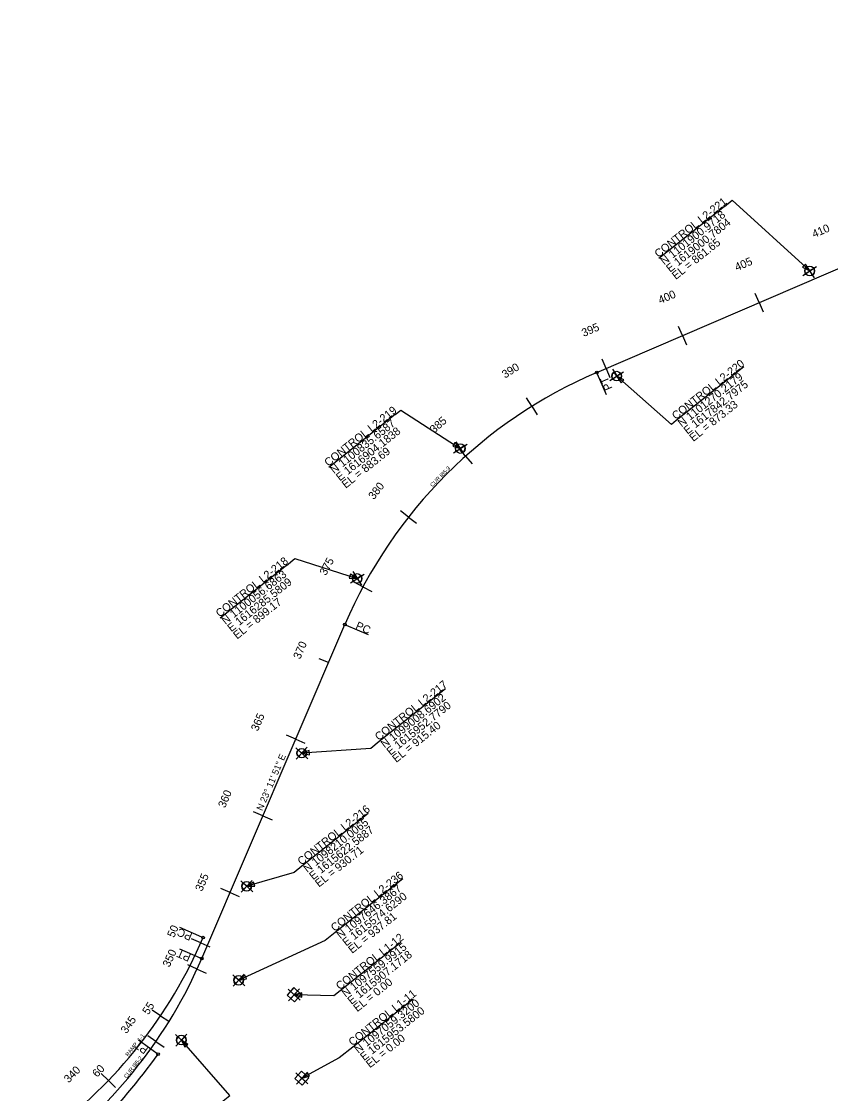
# Model space of a CAD drawing. Extents: x 1603447 to 1622636, y 1083818 to 1103958.
# Drawn here: x 1614271 to 1619126, y 1096967 to 1103398 of the extents above; entities that cross this region are included whole.
import ezdxf

# ---------------------------------------------------------------- set-up
doc = ezdxf.new("R2010")
doc.units = 0
for name, color, linetype in [('Level 1', 7, 'Continuous'), ('RD_HC_Points', 7, 'Continuous'), ('RD_HC_SUR_Bearing_TX400', 7, 'Continuous'), ('RD_HC_SUR_CL400', 7, 'Continuous'), ('RD_HC_SUR_PC_PT_400', 7, 'Continuous'), ('RD_HC_SUR_Tic400', 7, 'Continuous'), ('RD_HC_SUR_TX_Sta400', 7, 'Continuous'), ('RD_SHT_Misc1', 7, 'Continuous'), ('RD_TX_Misc1', 7, 'Continuous')]:
    doc.layers.add(name, color=color, linetype=linetype)

msp = doc.modelspace()

# ---------------------------------------------------------------- linework, layer by layer
at = {"layer": 'RD_HC_Points'}
for p, q in [((1618489.5, 1102287.9), (1618095.7, 1101974.7)), ((1618605.8, 1101325.6), (1618200.3, 1101003.1)), ((1616512.6, 1101039.1), (1616114.6, 1100722.5)), ((1615860.9, 1100134.8), (1615462.9, 1099818.2)), ((1616816.1, 1099394.5), (1616417.9, 1099077.8)), ((1616352.2, 1098647.2), (1615954, 1098330.5)), ((1616558.5, 1098255.1), (1616153.1, 1097932.6)), ((1616548.3, 1097872.8), (1616183.9, 1097582.9)), ((1616621.1, 1097533.5), (1616259.8, 1097246.2))]:
    msp.add_line(p, q, dxfattribs=at)
for points in [[(1618489.5, 1102287.9), (1618535.6, 1102324.6), (1619000.8, 1101901)], [(1618200.3, 1101003.1), (1618171.1, 1100979.8), (1617842.8, 1101270.2)], [(1616512.6, 1101039.1), (1616547.5, 1101066.8), (1616904.2, 1100835.7)], [(1615860.9, 1100134.8), (1615912.1, 1100175.5), (1616285.6, 1100056.7)], [(1616417.9, 1099077.8), (1616366.7, 1099037.1), (1615952.8, 1099008.7)], [(1615954, 1098330.5), (1615907.3, 1098293.4), (1615622.6, 1098210)], [(1616153.1, 1097932.6), (1616094, 1097885.6), (1615574.6, 1097646.4)], [(1616183.9, 1097582.9), (1616145.4, 1097552.3), (1615907.2, 1097560)], [(1615470.7, 1096915.2), (1615521.2, 1096955.3), (1615230.5, 1097288.1)], [(1616259.8, 1097246.2), (1616177.3, 1097180.5), (1615953.6, 1097059.3)]]:
    msp.add_lwpolyline(points, dxfattribs=at)
for points in [[(1618958.1, 1101923), (1619000.8, 1101901), (1618974.9, 1101941.4)], [(1617885.8, 1101248.8), (1617842.8, 1101270.2), (1617869.3, 1101230.2)], [(1616858.5, 1100850.4), (1616904.2, 1100835.7), (1616872, 1100871.3)], [(1616237.6, 1100058.9), (1616285.6, 1100056.7), (1616245.2, 1100082.6)], [(1615998.2, 1099024.3), (1615952.8, 1099008.7), (1615999.9, 1098999.5)], [(1615663.6, 1098235), (1615622.6, 1098210), (1615670.6, 1098211.1)], [(1615611.5, 1097677.1), (1615574.6, 1097646.4), (1615621.9, 1097654.5)], [(1615953.9, 1097570.9), (1615907.2, 1097560), (1615953.1, 1097546.1)], [(1615270.3, 1097261.4), (1615230.5, 1097288.1), (1615251.6, 1097245)], [(1615988.4, 1097092.3), (1615953.6, 1097059.3), (1616000.3, 1097070.5)]]:
    msp.add_lwpolyline(points, close=True, dxfattribs=at)
at = {"layer": 'RD_HC_SUR_CL400'}
for p, q in [((1617722.6, 1101292.3), (1622627.7, 1103397.5)), ((1615352.6, 1097776.8), (1616211.1, 1099780))]:
    msp.add_line(p, q, dxfattribs=at)
for centre, radius, start, end in [((1618858.6, 1098645.4), 2880.3, 113.22835, 156.80236), ((1612727.4, 1099031), 2865, 306.62559, 336.80236), ((1612720.8, 1098904.6), 2863.3, 306.62559, 336.80236), ((1612003.8, 1099419.5), 3800, 306.62559, 324.31797)]:
    msp.add_arc(centre, radius, start, end, dxfattribs=at)
at = {"layer": 'RD_HC_SUR_PC_PT_400'}
for p, q in [((1617725.7, 1101284.9), (1617779.3, 1101160.1)), ((1616218.5, 1099776.9), (1616350.6, 1099720.2)), ((1615353.4, 1097905.6), (1615221.3, 1097962.2)), ((1615345.3, 1097779.9), (1615220.4, 1097833.4)), ((1615083.9, 1097207.7), (1614973.6, 1097286.9))]:
    msp.add_line(p, q, dxfattribs=at)
for centre in [(1617722.6, 1101292.3), (1616211.1, 1099780), (1615360.8, 1097902.4), (1615352.6, 1097776.8), (1615090.4, 1097203)]:
    msp.add_circle(centre, 8, dxfattribs=at)
at = {"layer": 'RD_HC_SUR_Tic400'}
for p, q in [((1619065.3, 1101868.6), (1619065.3, 1101868.6)), ((1618881.5, 1101789.7), (1618881.5, 1101789.7)), ((1618973.4, 1101829.1), (1618973.4, 1101829.1)), ((1618697.7, 1101710.8), (1618674.1, 1101766)), ((1618789.6, 1101750.3), (1618789.6, 1101750.3)), ((1618605.9, 1101671.4), (1618605.9, 1101671.4)), ((1618697.7, 1101710.8), (1618721.4, 1101655.7)), ((1618514, 1101631.9), (1618514, 1101631.9)), ((1618238.3, 1101513.6), (1618214.6, 1101568.8)), ((1618330.2, 1101553.1), (1618330.2, 1101553.1)), ((1618422.1, 1101592.5), (1618422.1, 1101592.5)), ((1618146.4, 1101474.2), (1618146.4, 1101474.2)), ((1618238.3, 1101513.6), (1618261.9, 1101458.5)), ((1618054.5, 1101434.7), (1618054.5, 1101434.7)), ((1617778.8, 1101316.4), (1617755.1, 1101371.6)), ((1617870.7, 1101355.9), (1617870.7, 1101355.9)), ((1617962.6, 1101395.3), (1617962.6, 1101395.3)), ((1617687, 1101276.7), (1617687, 1101276.7)), ((1617778.8, 1101316.4), (1617802.5, 1101261.3)), ((1617596.4, 1101234.5), (1617596.4, 1101234.5)), ((1617507.3, 1101189.1), (1617507.3, 1101189.1)), ((1617334.1, 1101089.2), (1617302.3, 1101140.1)), ((1617334.1, 1101089.2), (1617365.8, 1101038.3)), ((1617419.8, 1101140.7), (1617419.8, 1101140.7)), ((1617250.1, 1101034.8), (1617250.1, 1101034.8)), ((1617168.2, 1100977.6), (1617168.2, 1100977.6)), ((1617088.2, 1100917.5), (1617088.2, 1100917.5)), ((1616934.9, 1100789.2), (1616894.8, 1100833.9)), ((1617010.4, 1100854.7), (1617010.4, 1100854.7)), ((1616934.9, 1100789.2), (1616974.9, 1100744.5)), ((1616861.6, 1100721.1), (1616861.6, 1100721.1)), ((1616790.8, 1100650.6), (1616790.8, 1100650.6)), ((1616722.4, 1100577.6), (1616722.4, 1100577.6)), ((1616656.6, 1100502.3), (1616656.6, 1100502.3)), ((1616593.5, 1100424.7), (1616546.3, 1100461.8)), ((1616593.5, 1100424.7), (1616640.7, 1100387.6)), ((1616533.1, 1100345), (1616533.1, 1100345)), ((1616475.5, 1100263.3), (1616475.5, 1100263.3)), ((1616420.8, 1100179.6), (1616420.8, 1100179.6)), ((1616369, 1100094), (1616369, 1100094)), ((1616320.2, 1100006.8), (1616267.4, 1100035.1)), ((1616320.2, 1100006.8), (1616373.1, 1099978.4)), ((1616274.5, 1099917.8), (1616274.5, 1099917.8)), ((1616231.9, 1099827.4), (1616231.9, 1099827.4)), ((1616192.1, 1099735.6), (1616192.1, 1099735.6)), ((1616152.7, 1099643.7), (1616152.7, 1099643.7)), ((1616113.3, 1099551.8), (1616058.2, 1099575.4)), ((1616073.9, 1099459.9), (1616073.9, 1099459.9)), ((1616034.5, 1099368), (1616034.5, 1099368)), ((1615995.1, 1099276.1), (1615995.1, 1099276.1)), ((1615955.7, 1099184.1), (1615955.7, 1099184.1)), ((1615916.4, 1099092.2), (1615861.2, 1099115.9)), ((1615916.4, 1099092.2), (1615971.5, 1099068.6)), ((1615877, 1099000.3), (1615877, 1099000.3)), ((1615837.6, 1098908.4), (1615837.6, 1098908.4)), ((1615798.2, 1098816.5), (1615798.2, 1098816.5)), ((1615758.8, 1098724.6), (1615758.8, 1098724.6)), ((1615719.4, 1098632.6), (1615664.2, 1098656.3)), ((1615719.4, 1098632.6), (1615774.5, 1098609)), ((1615680, 1098540.7), (1615680, 1098540.7)), ((1615640.6, 1098448.8), (1615640.6, 1098448.8)), ((1615601.2, 1098356.9), (1615601.2, 1098356.9)), ((1615561.8, 1098265), (1615561.8, 1098265)), ((1615522.4, 1098173.1), (1615467.3, 1098196.7)), ((1615522.4, 1098173.1), (1615577.6, 1098149.4)), ((1615483.1, 1098081.2), (1615483.1, 1098081.2)), ((1615443.7, 1097989.2), (1615443.7, 1097989.2)), ((1615347.1, 1097871), (1615292.2, 1097895.3)), ((1615347.1, 1097871), (1615401.9, 1097846.7)), ((1615404.3, 1097897.3), (1615404.3, 1097897.3)), ((1615364.9, 1097805.4), (1615364.9, 1097805.4)), ((1615324.7, 1097713.8), (1615270.2, 1097738.8)), ((1615305, 1097780.3), (1615305, 1097780.3)), ((1615259.8, 1097691.1), (1615259.8, 1097691.1)), ((1615324.7, 1097713.8), (1615379.3, 1097688.9)), ((1615281.6, 1097623.6), (1615281.6, 1097623.6)), ((1615211.5, 1097603.5), (1615211.5, 1097603.5)), ((1615160.1, 1097517.7), (1615160.1, 1097517.7)), ((1615235.3, 1097535), (1615235.3, 1097535)), ((1615105.9, 1097433.7), (1615056, 1097467.2)), ((1615105.9, 1097433.7), (1615155.7, 1097400.3)), ((1615185.9, 1097448), (1615185.9, 1097448)), ((1615048.7, 1097351.7), (1615048.7, 1097351.7)), ((1615133.6, 1097362.8), (1615133.6, 1097362.8)), ((1615078.2, 1097279.5), (1615028.8, 1097313.6)), ((1614988.7, 1097271.7), (1614988.7, 1097271.7)), ((1615078.2, 1097279.5), (1615127.6, 1097245.5)), ((1614925.9, 1097193.9), (1614925.9, 1097193.9)), ((1615020.1, 1097198.2), (1615020.1, 1097198.2)), ((1614860.4, 1097118.3), (1614860.4, 1097118.3)), ((1614959.1, 1097119), (1614959.1, 1097119)), ((1615048.9, 1097146.3), (1615048.9, 1097146.3)), ((1614792.4, 1097045), (1614749.1, 1097086.6)), ((1614792.4, 1097045), (1614835.6, 1097003.4)), ((1614895.4, 1097041.9), (1614895.4, 1097041.9)), ((1614988, 1097066.9), (1614988, 1097066.9)), ((1614721.8, 1096974.2), (1614721.8, 1096974.2)), ((1614829, 1096967.1), (1614829, 1096967.1)), ((1614925.1, 1096989.2), (1614925.1, 1096989.2))]:
    msp.add_line(p, q, dxfattribs=at)
at = {"layer": 'RD_SHT_Misc1'}
for p, q in [((1618959.7, 1101874.7), (1619041.9, 1101927.2)), ((1618974.6, 1101942.1), (1619027, 1101859.9)), ((1619000.8, 1101901), (1618985.3, 1101925.2)), ((1619025, 1101916.4), (1619000.8, 1101901)), ((1618976.5, 1101885.5), (1619000.8, 1101901)), ((1619000.8, 1101901), (1619016.2, 1101876.7)), ((1617801.7, 1101244), (1617883.9, 1101296.4)), ((1617816.6, 1101311.3), (1617869, 1101229.1)), ((1617842.8, 1101270.2), (1617827.3, 1101294.5)), ((1617867, 1101285.7), (1617842.8, 1101270.2)), ((1617818.6, 1101254.8), (1617842.8, 1101270.2)), ((1617842.8, 1101270.2), (1617858.3, 1101246)), ((1616863.1, 1100809.4), (1616945.3, 1100861.9)), ((1616878, 1100876.8), (1616930.4, 1100794.6)), ((1616879.9, 1100820.2), (1616904.2, 1100835.7)), ((1616904.2, 1100835.7), (1616888.7, 1100859.9)), ((1616928.4, 1100851.1), (1616904.2, 1100835.7)), ((1616904.2, 1100835.7), (1616919.7, 1100811.4)), ((1616244.5, 1100030.5), (1616326.7, 1100082.9)), ((1616259.4, 1100097.8), (1616311.8, 1100015.6)), ((1616261.3, 1100041.2), (1616285.6, 1100056.7)), ((1616285.6, 1100056.7), (1616270.1, 1100080.9)), ((1616309.8, 1100072.2), (1616285.6, 1100056.7)), ((1616285.6, 1100056.7), (1616301, 1100032.5)), ((1615916.8, 1099041.6), (1615988.7, 1098975.7)), ((1615919.8, 1098972.8), (1615985.7, 1099044.6)), ((1615952.8, 1099008.7), (1615931.6, 1099028.1)), ((1615972.2, 1099029.9), (1615952.8, 1099008.7)), ((1615933.4, 1098987.5), (1615952.8, 1099008.7)), ((1615952.8, 1099008.7), (1615974, 1098989.3)), ((1615586.7, 1098242.9), (1615658.5, 1098177.1)), ((1615589.6, 1098174.1), (1615655.5, 1098245.9)), ((1615622.6, 1098210), (1615601.4, 1098229.4)), ((1615603.2, 1098188.8), (1615622.6, 1098210)), ((1615642, 1098231.2), (1615622.6, 1098210)), ((1615622.6, 1098210), (1615643.8, 1098190.6)), ((1615538.7, 1097679.3), (1615610.6, 1097613.4)), ((1615541.7, 1097610.4), (1615607.6, 1097682.3)), ((1615574.6, 1097646.4), (1615553.4, 1097665.8)), ((1615555.2, 1097625.2), (1615574.6, 1097646.4)), ((1615594.1, 1097667.6), (1615574.6, 1097646.4)), ((1615574.6, 1097646.4), (1615595.8, 1097627)), ((1615871.2, 1097592.9), (1615943.1, 1097527.1)), ((1615874.2, 1097524.1), (1615940.1, 1097595.9)), ((1615885.1, 1097580.3), (1615907.2, 1097560)), ((1615907.2, 1097560), (1615886.9, 1097537.9)), ((1615907.2, 1097560), (1615927.4, 1097582.1)), ((1615929.3, 1097539.7), (1615907.2, 1097560)), ((1615194.5, 1097321.1), (1615266.4, 1097255.2)), ((1615197.5, 1097252.2), (1615263.4, 1097324.1)), ((1615230.5, 1097288.1), (1615209.3, 1097307.6)), ((1615211, 1097266.9), (1615230.5, 1097288.1)), ((1615249.9, 1097309.3), (1615230.5, 1097288.1)), ((1615230.5, 1097288.1), (1615251.6, 1097268.7)), ((1615920.6, 1097023.4), (1615986.5, 1097095.3)), ((1615917.6, 1097092.3), (1615989.5, 1097026.4)), ((1615931.5, 1097079.6), (1615953.6, 1097059.3)), ((1615953.6, 1097059.3), (1615933.3, 1097037.2)), ((1615953.6, 1097059.3), (1615973.9, 1097081.4)), ((1615975.7, 1097039.1), (1615953.6, 1097059.3))]:
    msp.add_line(p, q, dxfattribs=at)
for points in [[(1615909, 1097517.6), (1615949.6, 1097561.8), (1615905.3, 1097602.4), (1615864.8, 1097558.1)], [(1615955.4, 1097016.9), (1615996, 1097061.2), (1615951.7, 1097101.7), (1615911.2, 1097057.5)]]:
    msp.add_lwpolyline(points, close=True, dxfattribs=at)
for points in [[(1615927.4, 1097582.1), (1615905.3, 1097602.4), (1615885.1, 1097580.3)], [(1615886.9, 1097537.9), (1615909, 1097517.6)], [(1615909, 1097517.6), (1615929.3, 1097539.7)], [(1615973.9, 1097081.4), (1615951.7, 1097101.7), (1615931.5, 1097079.6)], [(1615933.3, 1097037.2), (1615955.4, 1097016.9)], [(1615955.4, 1097016.9), (1615975.7, 1097039.1)]]:
    msp.add_lwpolyline(points, dxfattribs=at)
for centre in [(1619000.8, 1101901), (1617842.8, 1101270.2), (1616904.2, 1100835.7), (1616285.6, 1100056.7), (1615952.8, 1099008.7), (1615622.6, 1098210), (1615574.6, 1097646.4), (1615230.5, 1097288.1)]:
    msp.add_circle(centre, 28.8, dxfattribs=at)
for centre, start, end in [((1619000.8, 1101901), 122.54454, 212.54454), ((1619000.8, 1101901), 302.54454, 32.54454), ((1617842.8, 1101270.2), 122.54454, 212.54454), ((1617842.8, 1101270.2), 302.54454, 32.54454), ((1616904.2, 1100835.7), 122.54454, 212.54454), ((1616904.2, 1100835.7), 302.54454, 32.54454), ((1616285.6, 1100056.7), 122.54454, 212.54454), ((1616285.6, 1100056.7), 302.54454, 32.54454), ((1615952.8, 1099008.7), 137.49194, 227.49194), ((1615952.8, 1099008.7), 317.49194, 47.49194), ((1615622.6, 1098210), 137.49194, 227.49194), ((1615622.6, 1098210), 317.49194, 47.49194), ((1615574.6, 1097646.4), 137.49194, 227.49194), ((1615574.6, 1097646.4), 317.49194, 47.49194), ((1615230.5, 1097288.1), 137.49194, 227.49194), ((1615230.5, 1097288.1), 317.49194, 47.49194)]:
    msp.add_arc(centre, 28.8, start, end, dxfattribs=at)

# ---------------------------------------------------------------- texts
at = {"layer": 'Level 1'}
for s, rotation, p in [('405', 23.22835, (1618563.8, 1101899.3)), ('395', 23.22835, (1617644.9, 1101504.9)), ('385', 41.90308, (1616747.6, 1100924.8)), ('375', 61.79516, (1616098, 1100070.6)), ('365', 66.80236, (1615689.4, 1099136.4)), ('355', 66.80236, (1615354.7, 1098175.9)), ('55', 56.11675, (1615031.8, 1097436)), ('345', 55.41936, (1614901.5, 1097322.4))]:
    msp.add_text(s, height=48, rotation=rotation, dxfattribs=at).set_placement(p)
at = {"layer": 'RD_HC_Points'}
for s, p in [('CONTROL L2-221', (1618093.3, 1101977.9)), ('N 1101900.9718', (1618128.1, 1101934.1)), ('E 1619000.7804', (1618163, 1101890.2)), ('EL = 861.65', (1618197.8, 1101846.4)), ('CONTROL L2-220', (1618197.8, 1101006.2)), ('N 1101270.2179', (1618232.7, 1100962.4)), ('E 1617842.7975', (1618267.6, 1100918.5)), ('CONTROL L2-219', (1616112.1, 1100725.7)), ('EL = 873.33', (1618302.4, 1100874.7)), ('N 1100835.6587', (1616147, 1100681.8)), ('E 1616904.1838', (1616181.9, 1100638)), ('EL = 883.69', (1616216.7, 1100594.2)), ('CONTROL L2-218', (1615460.4, 1099821.3)), ('N 1100056.6863', (1615495.2, 1099777.5)), ('E 1616285.5809', (1615530.1, 1099733.7)), ('EL = 899.17', (1615565, 1099689.8)), ('CONTROL L2-217', (1616415.4, 1099080.9)), ('N 1099008.6902', (1616450.3, 1099037.1)), ('E 1615952.7790', (1616485.2, 1098993.3)), ('EL = 915.40', (1616520, 1098949.4)), ('CONTROL L2-216', (1615951.5, 1098333.6)), ('N 1098210.0065', (1615986.3, 1098289.8)), ('E 1615622.5887', (1616021.2, 1098246)), ('EL = 930.71', (1616056.1, 1098202.1)), ('CONTROL L2-236', (1616150.6, 1097935.7)), ('N 1097646.3867', (1616185.5, 1097891.9)), ('E 1615574.6290', (1616220.3, 1097848.1)), ('EL = 937.81', (1616255.2, 1097804.3)), ('CONTROL L1-12', (1616181.4, 1097586.1)), ('N 1097559.9915', (1616216.2, 1097542.2)), ('E 1615907.1718', (1616251.1, 1097498.4)), ('EL = 0.00', (1616286, 1097454.6)), ('CONTROL L1-11', (1616257.3, 1097249.3)), ('N 1097059.3200', (1616292.2, 1097205.5)), ('E 1615953.5800', (1616327, 1097161.6)), ('EL = 0.00', (1616361.9, 1097117.8))]:
    msp.add_text(s, height=48, rotation=38.4995, dxfattribs=at).set_placement(p)
at = {"layer": 'RD_HC_SUR_Bearing_TX400'}
msp.add_text('N 23%%d 11\' 51" E', height=40, rotation=66.80236, dxfattribs=at).set_placement((1615716.1, 1098659.9))
at = {"layer": 'RD_HC_SUR_PC_PT_400'}
for s, rotation, p in [('PT', 113.22835, (1617817.9, 1101197.1)), ('PC', 336.80236, (1616271.6, 1099756.2)), ('PC', 156.80236, (1615300.2, 1097926.2)), ('PT', 156.80236, (1615292.1, 1097800.5)), ('PT', 144.31797, (1615036.5, 1097239.3))]:
    msp.add_text(s, height=48, rotation=rotation, dxfattribs=at).set_placement(p)
at = {"layer": 'RD_HC_SUR_TX_Sta400'}
for s, rotation, p in [('410', 23.22835, (1619027.3, 1102098.2)), ('400', 23.22835, (1618104.1, 1101702)), ('390', 31.95703, (1617172.8, 1101255)), ('380', 51.84912, (1616385.5, 1100525.8)), ('370', 66.80236, (1615943.3, 1099568.2)), ('360', 66.80236, (1615492.4, 1098676.6)), ('50', 66.11601, (1615186.5, 1097898.6)), ('350', 65.42456, (1615158.8, 1097720.8)), ('340', 45.41416, (1614554.1, 1097027.7)), ('60', 46.11749, (1614724.9, 1097061.2))]:
    msp.add_text(s, height=48, rotation=rotation, dxfattribs=at).set_placement(p)
at = {"layer": 'RD_TX_Misc1'}
for s, rotation, p in [('CUR I85-3', 45.78261, (1616737.4, 1100603.3)), ('RAMP_1-1', 51.53785, (1614910.7, 1097186.9)), ('CUR I85-2', 51.73146, (1614901.9, 1097056.3))]:
    msp.add_text(s, height=24, rotation=rotation, dxfattribs=at).set_placement(p)

doc.saveas('drawing.dxf')
